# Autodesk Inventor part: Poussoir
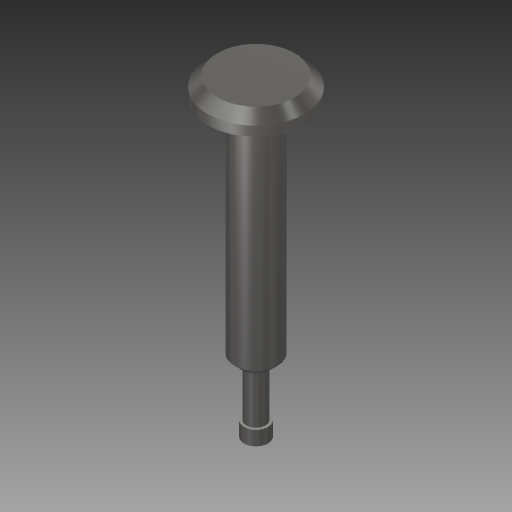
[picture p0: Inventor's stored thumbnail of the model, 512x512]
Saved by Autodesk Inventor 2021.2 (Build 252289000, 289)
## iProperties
Created: 2018-06
Part Number: Poussoir
Material: Acier inoxydable
Document SubType Name: Modeling
Designer: Fabian Perrée
Density: 8 g/cm^3
Appearance: Semi-poli
Author: Fabian Perrée
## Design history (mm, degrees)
sketch "Esquisse1"
  geometry: L1 (0, 0)-(0, 32.5); L2 (0, 32.5)-(4, 32.5); L3 (5, 31.5)-(5, 30.5); L4 (5, 30.5)-(2.25, 30.5); L5 (1.25, 6.5)-(1, 6.5); L6 (1, 6.5)-(1, 1.5); L7 (1, 1.5)-(1.25, 1.5); L8 (1.25, 1.5)-(1.25, 0); L9 (1.25, 0)-(0, 0); L10 (2.25, 30.5)-(2.25, 7.5); L11 (2.25, 7.5)-(1.25, 6.5); L12 (4, 32.5)-(5, 31.5); 2 further points
  constraints: 24 end point, 5 perpendicular, 4 point on line, 2 vertical, 1 horizontal
  dimensions: "d0" = 32.5 distance of L1.start L1.end; "d1" = 2 distance of point (5, 32.5) L3.end; "d3" = 2 diameter of L6 L1; "d4" = 2.5 diameter of L8 L1; "d5" = 4.5 diameter of L10 L1; "d6" = 24 distance from line of L4 L5.end; "d7" = 1.5 distance of L7.end L8.end; "d8" = 10 diameter of L3 L1; "d9" = 1 distance of L10.end point (2.25, 6.5); "d10" = 1 distance of L5.start point (2.25, 6.5) (= d9); "d11" = 1 distance of L2.end point (5, 32.5) (= d9); "d12" = 1 distance of L3.start point (5, 32.5) (= d11)
revolve "Révolution1" sketch "Esquisse1" stored, may be unused: angle "d13" = 90 deg
node "Solide1"
